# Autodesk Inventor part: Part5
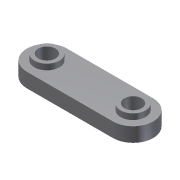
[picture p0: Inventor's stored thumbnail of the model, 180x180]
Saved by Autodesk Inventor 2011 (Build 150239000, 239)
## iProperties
Shininess: 77.0
Length Units: 11269
Angle Units: 11279
Time Units: 11290
Mass Units: 11283
Length Display Precision: 3
Angle Display Precision: 2
Created: 2002-01
Part Number: Part5
Document SubType Name: Modeling
Designer: ***
Density: 1 g/cm^3
Density: 0.0
Volumn: 0.0
Area: 0.0
PropertySet Name: Model Information
Control State: 0
Master: False
Checked Out: False
Author: ***
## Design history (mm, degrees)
sketch "Sketch1"
  geometry: L1 (-33.118, 12.346)-(26.882, 12.361); L2 (-33.111, -15.654)-(26.889, -15.639); C1 r 6 at (-33.114, -1.654); C2 r 6 at (26.886, -1.639); A1 r 14 centre (-33.114, -1.654) between (-33.118, 12.346) and (-33.111, -15.654); A2 r 14 centre (26.886, -1.639) between (26.889, -15.639) and (26.882, 12.361)
  constraints: 4 centre point, 4 end point, 4 point on circle, 4 tangent, 2 coincident, 2 equal radius
  dimensions: "d0" = 60 distance of L1.start L1.end; "d1" = 14 radius of A1; "d2" = 12 diameter of C1
extrude "Extrusion1" new body sketch "Sketch1" distance "d3" = 10; taper "d4" = 0 deg
sketch "Sketch2"
  geometry: C1 r 6 at (26.886, -1.639) reference; C2 r 6 at (-33.114, -1.654) reference; C3 r 8.694 at (-33.114, -1.654); C4 r 8.694 at (26.886, -1.639)
  constraints: 2 centre point, 2 coincident, 1 equal radius
extrude "Extrusion2" join sketch "Sketch2" distance "d5" = 4; taper "d6" = 0 deg
body "Solid1"
